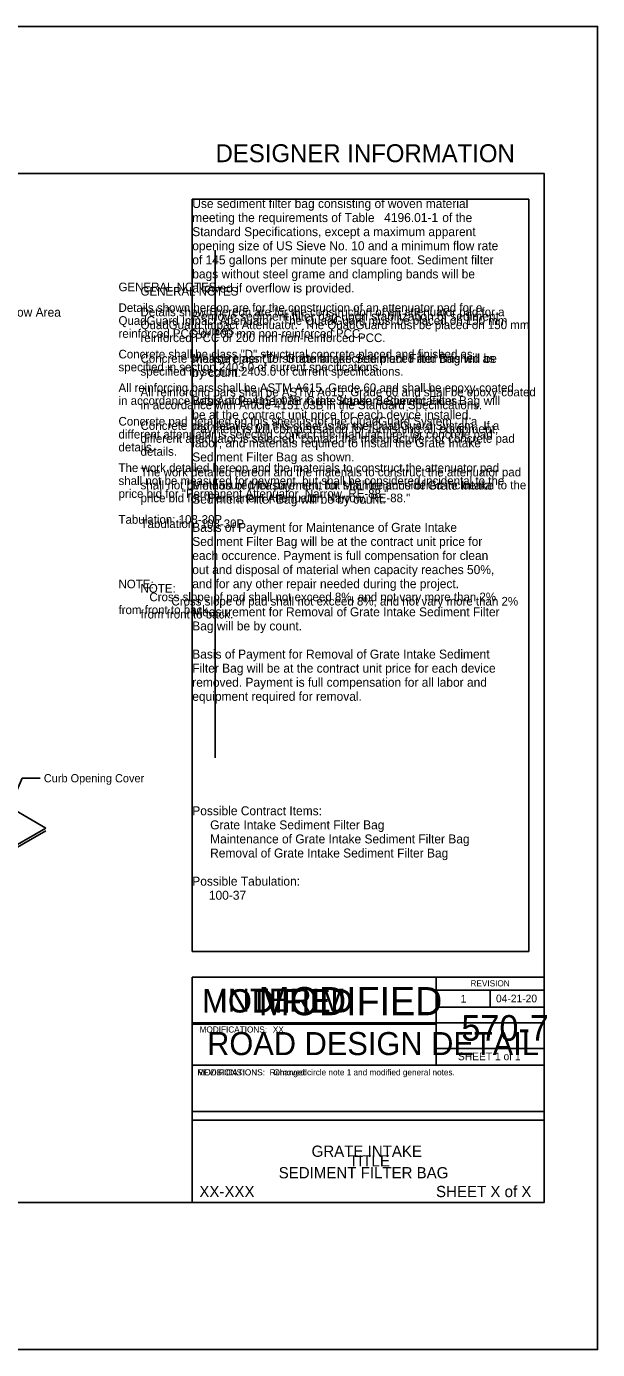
# Model space of a CAD drawing. Extents: x -4827 to -1483, y 910 to 4235.
# Drawn here: x -2600 to -1483, y 910 to 3494 of the extents above; entities that cross this region are included whole.
import ezdxf

# ---------------------------------------------------------------- set-up
doc = ezdxf.new("R2010")
doc.units = 0
for name, color, linetype in [('Default', 7, 'Continuous'), ('dsnNonPlotable', 7, 'Continuous'), ('dsnShtPlotShapeBatchPrint', 7, 'Continuous'), ('dsnStdBlock', 7, 'Continuous'), ('dsnstdblockInterim', 7, 'Continuous'), ('dsnStdBlockModified', 7, 'Continuous'), ('dsnStdBlockNotModified', 7, 'Continuous'), ('dsnStdBorder', 7, 'Continuous'), ('dsnstdModifiedBlock', 7, 'Continuous'), ('dsnStdNote', 7, 'Continuous'), ('Level 1', 7, 'Continuous')]:
    doc.layers.add(name, color=color, linetype=linetype)

msp = doc.modelspace()

# ---------------------------------------------------------------- linework, layer by layer
at = {"layer": 'Default'}
for p, q in [((-2948.6, 2151.9), (-2562, 1928.7)), ((-2562, 1928.7), (-2626.4, 1891.5)), ((-2626.4, 1886.1), (-2562, 1923.3))]:
    msp.add_line(p, q, dxfattribs=at)
at = {"layer": 'dsnNonPlotable'}
for p, q in [((-2275.8, 3157.3), (-2275.8, 1687.4)), ((-1617.8, 3157.3), (-2275.8, 3157.3)), ((-1617.8, 3157.3), (-1617.8, 1687.4)), ((-2230.8, 3057.3), (-2230.8, 2065.8)), ((-1617.8, 1687.4), (-2275.8, 1687.4))]:
    msp.add_line(p, q, dxfattribs=at)
at = {"layer": 'dsnShtPlotShapeBatchPrint'}
msp.add_lwpolyline([(-4827.3, 910.3), (-1483.3, 910.3), (-1483.3, 3494.3), (-4827.3, 3494.3)], close=True, dxfattribs=at)
at = {"layer": 'dsnStdBlock'}
for p, q in [((-1587.8, 3207.3), (-1587.8, 3207.3)), ((-1798.7, 1637.4), (-1798.7, 1546)), ((-1798.7, 1612.4), (-1587.8, 1612.4)), ((-1693.2, 1612.4), (-1693.2, 1579.2)), ((-1798.7, 1579.2), (-1587.8, 1579.2)), ((-2275.8, 1546), (-1798.7, 1546)), ((-1798.7, 1546), (-1798.7, 1466)), ((-1587.8, 1498.2), (-1798.7, 1498.2)), ((-2275.8, 1466), (-1587.8, 1466)), ((-2275.8, 1375), (-1587.8, 1375))]:
    msp.add_line(p, q, dxfattribs=at)
msp.add_lwpolyline([(-2573.1, 2026.1), (-2608.1, 2026.1), (-2686.9, 1845)], dxfattribs=at)
msp.add_lwpolyline([(-2275.8, 1637.4), (-1587.8, 1637.4), (-1587.8, 1197.3), (-2275.8, 1197.3)], close=True, dxfattribs=at)
at = {"layer": 'dsnStdBorder'}
msp.add_lwpolyline([(-4722.8, 3207.3), (-1587.8, 3207.3), (-1587.8, 1197.3), (-4722.8, 1197.3)], close=True, dxfattribs=at)
at = {"layer": 'dsnstdModifiedBlock'}
for p, q in [((-2275.8, 1548.3), (-1587.8, 1548.3)), ((-2275.8, 1358.3), (-1587.8, 1358.3))]:
    msp.add_line(p, q, dxfattribs=at)
msp.add_lwpolyline([(-2275.8, 1637.4), (-1587.8, 1637.4), (-1587.8, 1197.3), (-2275.8, 1197.3)], close=True, dxfattribs=at)

# ---------------------------------------------------------------- texts
at = {"layer": 'dsnStdBlock'}
for s, height, p in [('DESIGNER INFORMATION', 35, (-2230.2, 3229.3)), ('REVISION', 12, (-1731.7, 1619.5)), ('1', 15, (-1751, 1588)), ('04-21-20', 15, (-1681.9, 1588.5)), ('570-7', 50, (-1749.6, 1513.5)), ('ROAD DESIGN DETAIL', 45.001, (-2246.7, 1485.4)), ('SHEET 1 of 1', 15, (-1756.3, 1475.4)), ('Removed circle note 1 and modified general notes.', 12, (-2124.5, 1445.8)), (' GRATE INTAKE', 22, (-2050.6, 1286.7)), ('SEDIMENT FILTER BAG', 22, (-2106.8, 1244.7))]:
    msp.add_text(s, height=height, dxfattribs=at).set_placement(p)
at = {"layer": 'dsnstdblockInterim'}
msp.add_text('INTERIM', height=45, dxfattribs=at).set_placement((-2223.1, 1570.1))
at = {"layer": 'dsnStdBlockModified'}
for s, height, p in [('MODIFIED', 45, (-2256.2, 1569.2)), ('MODIFIED', 45, (-2256.1, 1568.5)), ('MODIFICATIONS:', 12, (-2265.8, 1445.7)), ('MODIFICATIONS:', 12, (-2265.5, 1445.7)), ('Changed                                                            ', 12, (-2116.5, 1445.8))]:
    msp.add_text(s, height=height, dxfattribs=at).set_placement(p)
at = {"layer": 'dsnStdBlockNotModified'}
msp.add_text('REVISIONS:', height=12, dxfattribs=at).set_placement((-2265.8, 1445.7))
at = {"layer": 'dsnstdModifiedBlock'}
for s, height, p in [('MODIFIED', 55, (-2146.4, 1563.3)), ('MODIFICATIONS:', 12, (-2261.5, 1529.4)), ('XX', 12, (-2118.2, 1529.4)), ('TITLE', 22, (-1969.4, 1267.9)), ('XX-XXX', 22, (-2261.9, 1208)), ('SHEET X of X', 22, (-1799.1, 1208))]:
    msp.add_text(s, height=height, dxfattribs=at).set_placement(p)
at = {"layer": 'dsnStdNote'}
for s, height, p in [('Use sediment filter bag consisting of woven material ', 17.5, (-2275.8, 3139.8)), ('meeting the requirements of Table ', 17.5, (-2275.8, 3112.3)), ('4196.01-1', 17.5, (-1900.5, 3112.3)), ('4196.01-1', 17.5, (-1900.5, 3112.3)), (' of the ', 17.5, (-1793.4, 3112.3)), ('Standard Specifications, except a maximum apparent ', 17.5, (-2275.8, 3084.8)), ('opening size of US Sieve No. 10 and a minimum flow rate ', 17.5, (-2275.8, 3057.3)), ('of 145 gallons per minute per square foot. Sediment filter ', 17.5, (-2275.8, 3029.8)), ('bags without steel grame and clampling bands will be ', 17.5, (-2275.8, 3002.3)), ('allowed if overflow is provided.', 17.5, (-2275.8, 2974.8)), ('Overflow Area', 17.5, (-2680.9, 2927.5)), ('Remove sediment filter bag upon stabilization of sediment ', 17.5, (-2275.8, 2919.8)), ('sources.', 17.5, (-2275.8, 2892.3)), ('Measurement for Grate Intake Sediment Filter Bag will be ', 17.5, (-2275.8, 2837.3)), ('by count.', 17.5, (-2275.8, 2809.8)), ('Basis of Payment for Grate Intake Sediment Filter Bag will ', 17.5, (-2275.8, 2754.8)), ('be at the contract unit price for each device installed. ', 17.5, (-2275.8, 2727.3)), ('Payment is full compensation for furnishing all equipment, ', 17.5, (-2275.8, 2699.8)), ('labor, and materials required to install the Grate Intake ', 17.5, (-2275.8, 2672.3)), ('Sediment Filter Bag as shown.', 17.5, (-2275.8, 2644.8)), ('Method of Measurement for Maintenance of Grate Intake ', 17.5, (-2275.8, 2589.8)), ('Sediment Filter Bag will be by count.', 17.5, (-2275.8, 2562.3)), ('Basis of Payment for Maintenance of Grate Intake ', 17.5, (-2275.8, 2507.3)), ('Sediment Filter Bag will be at the contract unit price for ', 17.5, (-2275.8, 2479.8)), ('each occurence. Payment is full compensation for clean ', 17.5, (-2275.8, 2452.3)), ('out and disposal of material when capacity reaches 50%, ', 17.5, (-2275.8, 2424.8)), ('and for any other repair needed during the project.', 17.5, (-2275.8, 2397.3)), ('Measurement for Removal of Grate Intake Sediment Filter ', 17.5, (-2275.8, 2342.3)), ('Bag will be by count.', 17.5, (-2275.8, 2314.8)), ('Basis of Payment for Removal of Grate Intake Sediment ', 17.5, (-2275.8, 2259.8)), ('Filter Bag will be at the contract unit price for each device ', 17.5, (-2275.8, 2232.3)), ('removed. Payment is full compensation for all labor and ', 17.5, (-2275.8, 2204.8)), ('equipment required for removal.', 17.5, (-2275.8, 2177.3)), ('Curb Opening Cover', 16, (-2566, 2018.1)), ('Possible Contract Items:', 17.5, (-2275.8, 1953.8)), ('Grate Intake Sediment Filter Bag', 17.5, (-2240.8, 1926.3)), ('Maintenance of Grate Intake Sediment Filter Bag', 17.5, (-2240.8, 1898.8)), ('Removal of Grate Intake Sediment Filter Bag', 17.5, (-2240.8, 1871.3)), ('Possible Tabulation:', 17.5, (-2275.8, 1816.3)), ('     100-37', 17.5, (-2275.8, 1788.8)), ('     100-37', 17.5, (-2275.8, 1788.8))]:
    msp.add_text(s, height=height, dxfattribs=at).set_placement(p)
at = {"layer": 'Level 1'}
for s, height, p in [('GENERAL NOTES', 16.825, (-2420, 2977.2)), ('GENERAL NOTES', 16.825, (-2376.9, 2968.7)), ('Details shown hereon are for the construction of an attenuator pad for a', 16.825, (-2420, 2936.8)), ('Details shown hereon are for the construction of an attenuator pad for a', 16.825, (-2376.9, 2928.4)), ('QuadGuard Impact Attenuator.  The QuadGuard must be placed on 150 mm', 16.825, (-2420, 2911.6)), ('QuadGuard Impact Attenuator.  The QuadGuard must be placed on 150 mm', 16.825, (-2376.9, 2903.2)), ('reinforced PCC or 200 mm non-reinforced PCC.', 16.825, (-2420, 2886.3)), ('reinforced PCC or 200 mm non-reinforced PCC.', 16.825, (-2376.9, 2877.9)), ('Concrete shall be class "D" structural concrete placed and finished as', 16.825, (-2420, 2846)), ('Concrete shall be class "D" structural concrete placed and finished as', 16.825, (-2376.9, 2837.6)), ('specified in section 2403.0 of current specifications.', 16.825, (-2420, 2820.8)), ('specified in section 2403.0 of current specifications.', 16.825, (-2376.9, 2812.3)), ('All reinforcing bars shall be ASTM A615, Grade 60 and shall be epoxy-coated', 16.825, (-2420, 2780.4)), ('in accordance with Article 4151.03B in the Standard Specifications.', 16.825, (-2420, 2755.2)), ('All reinforcing bars shall be ASTM A615, Grade 60 and shall be epoxy-coated', 16.825, (-2376.9, 2772)), ('in accordance with Article 4151.03B in the Standard Specifications.', 16.825, (-2376.9, 2746.8)), ('Concrete pad detailed on this sheet is for the QuadGuard System.  If a', 16.825, (-2420, 2714.9)), ('Concrete pad detailed on this sheet is for the QuadGuard System.  If a', 16.825, (-2376.9, 2706.4)), ('different attenuator is selected, contact the manufacturer for concrete pad', 16.825, (-2420, 2689.6)), ('different attenuator is selected, contact the manufacturer for concrete pad', 16.825, (-2376.9, 2681.2)), ('details.', 16.82, (-2420, 2664.4)), ('details.', 16.82, (-2376.9, 2655.9)), ('The work detailed hereon and the materials to construct the attenuator pad', 16.825, (-2420, 2624)), ('shall not be measured for payment, but shall be considered incidental to the', 16.825, (-2420, 2598.8)), ('The work detailed hereon and the materials to construct the attenuator pad', 16.825, (-2376.9, 2615.6)), ('price bid for "Permanent Attenuator, Narrow, RE-88."', 16.825, (-2420, 2573.6)), ('shall not be measured for payment, but shall be considered incidental to the', 16.825, (-2376.9, 2590.4)), ('price bid for "Permanent Attenuator, Narrow, RE-88."', 16.825, (-2376.9, 2565.1)), ('Tabulation: 108-30P', 16.825, (-2420, 2523.1)), ('Tabulation: 108-30P', 16.825, (-2376.9, 2514.7)), ('NOTE:', 16.82, (-2420, 2397.1)), ('NOTE:', 16.82, (-2376.9, 2388.6)), ('Cross slope of pad shall not exceed 8%, and not vary more than 2%', 16.825, (-2359.6, 2371.8)), ('Cross slope of pad shall not exceed 8%, and not vary more than 2%', 16.825, (-2316.5, 2363.4)), ('from front to back.', 16.825, (-2420, 2346.6)), ('from front to back.', 16.825, (-2376.9, 2338.1))]:
    msp.add_text(s, height=height, dxfattribs=at).set_placement(p)

doc.saveas('drawing.dxf')
